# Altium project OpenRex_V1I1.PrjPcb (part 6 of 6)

## Sheet [24] - HEADERS, UART.SchDoc
size A2; DocumentNumber: 24; SheetNumber: 24; SheetTotal: 31
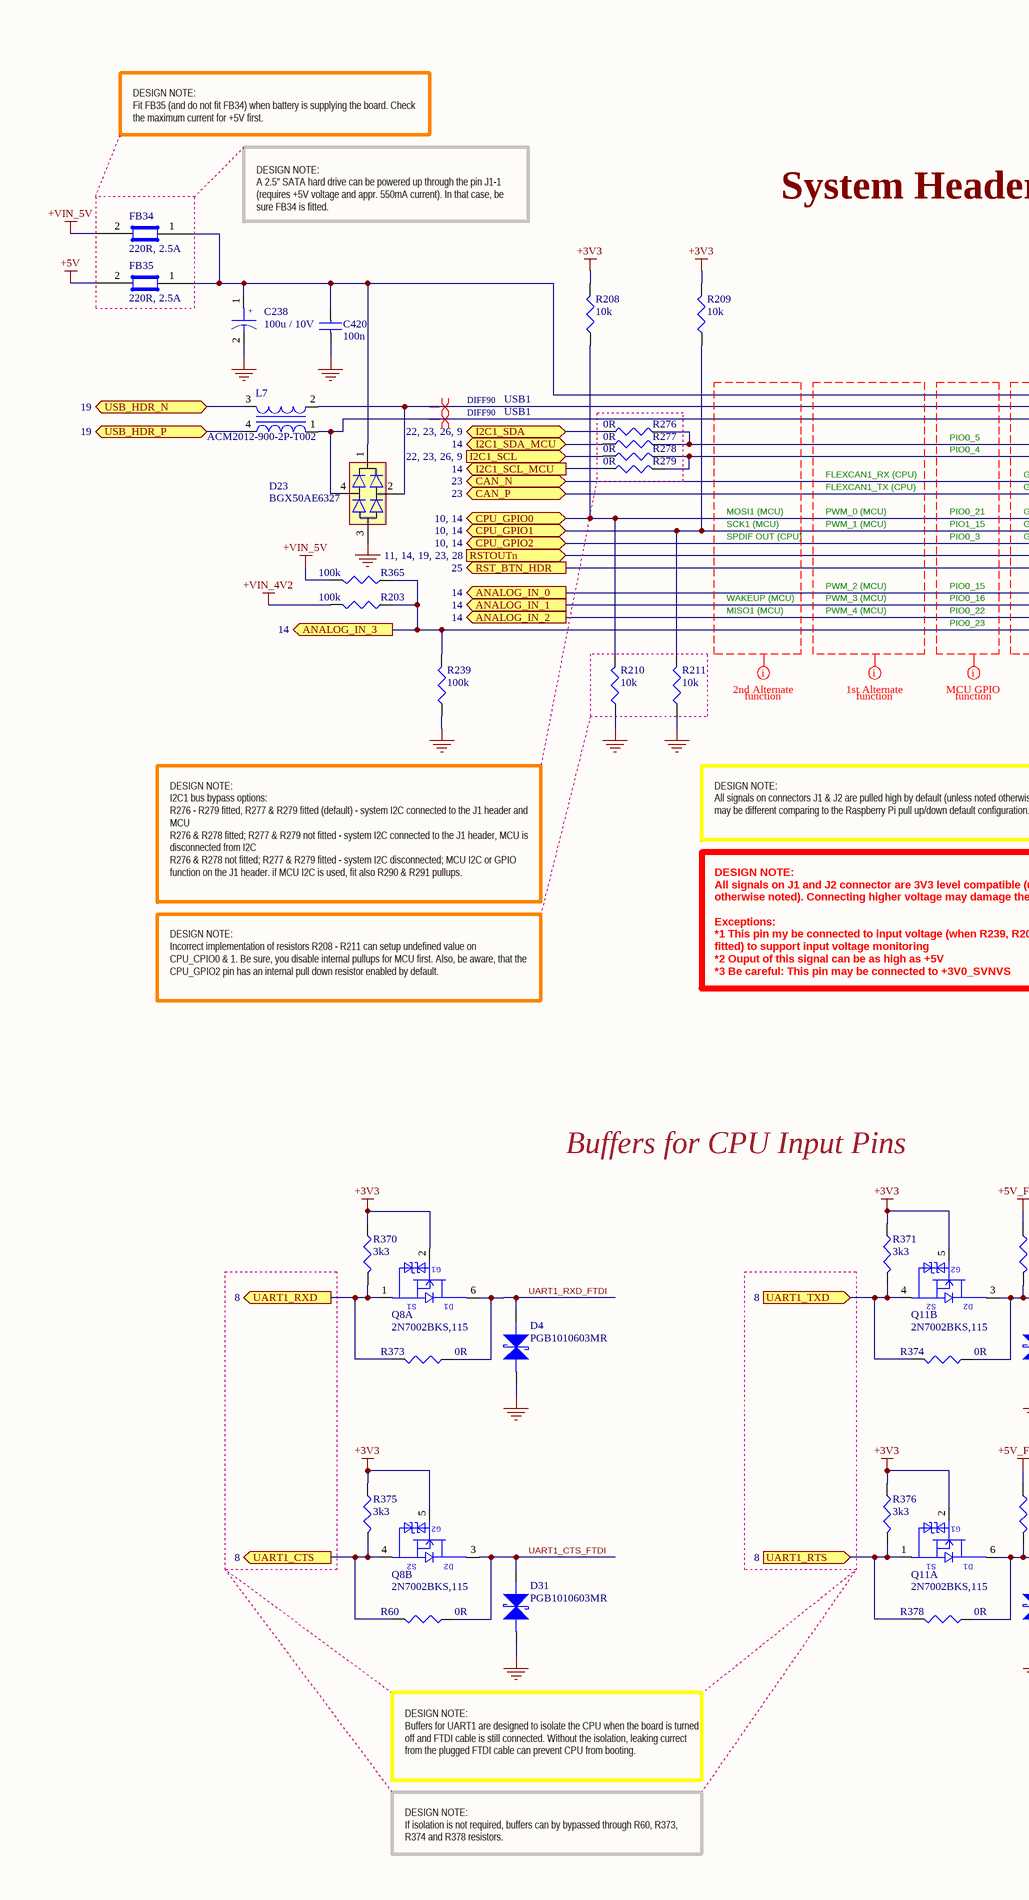
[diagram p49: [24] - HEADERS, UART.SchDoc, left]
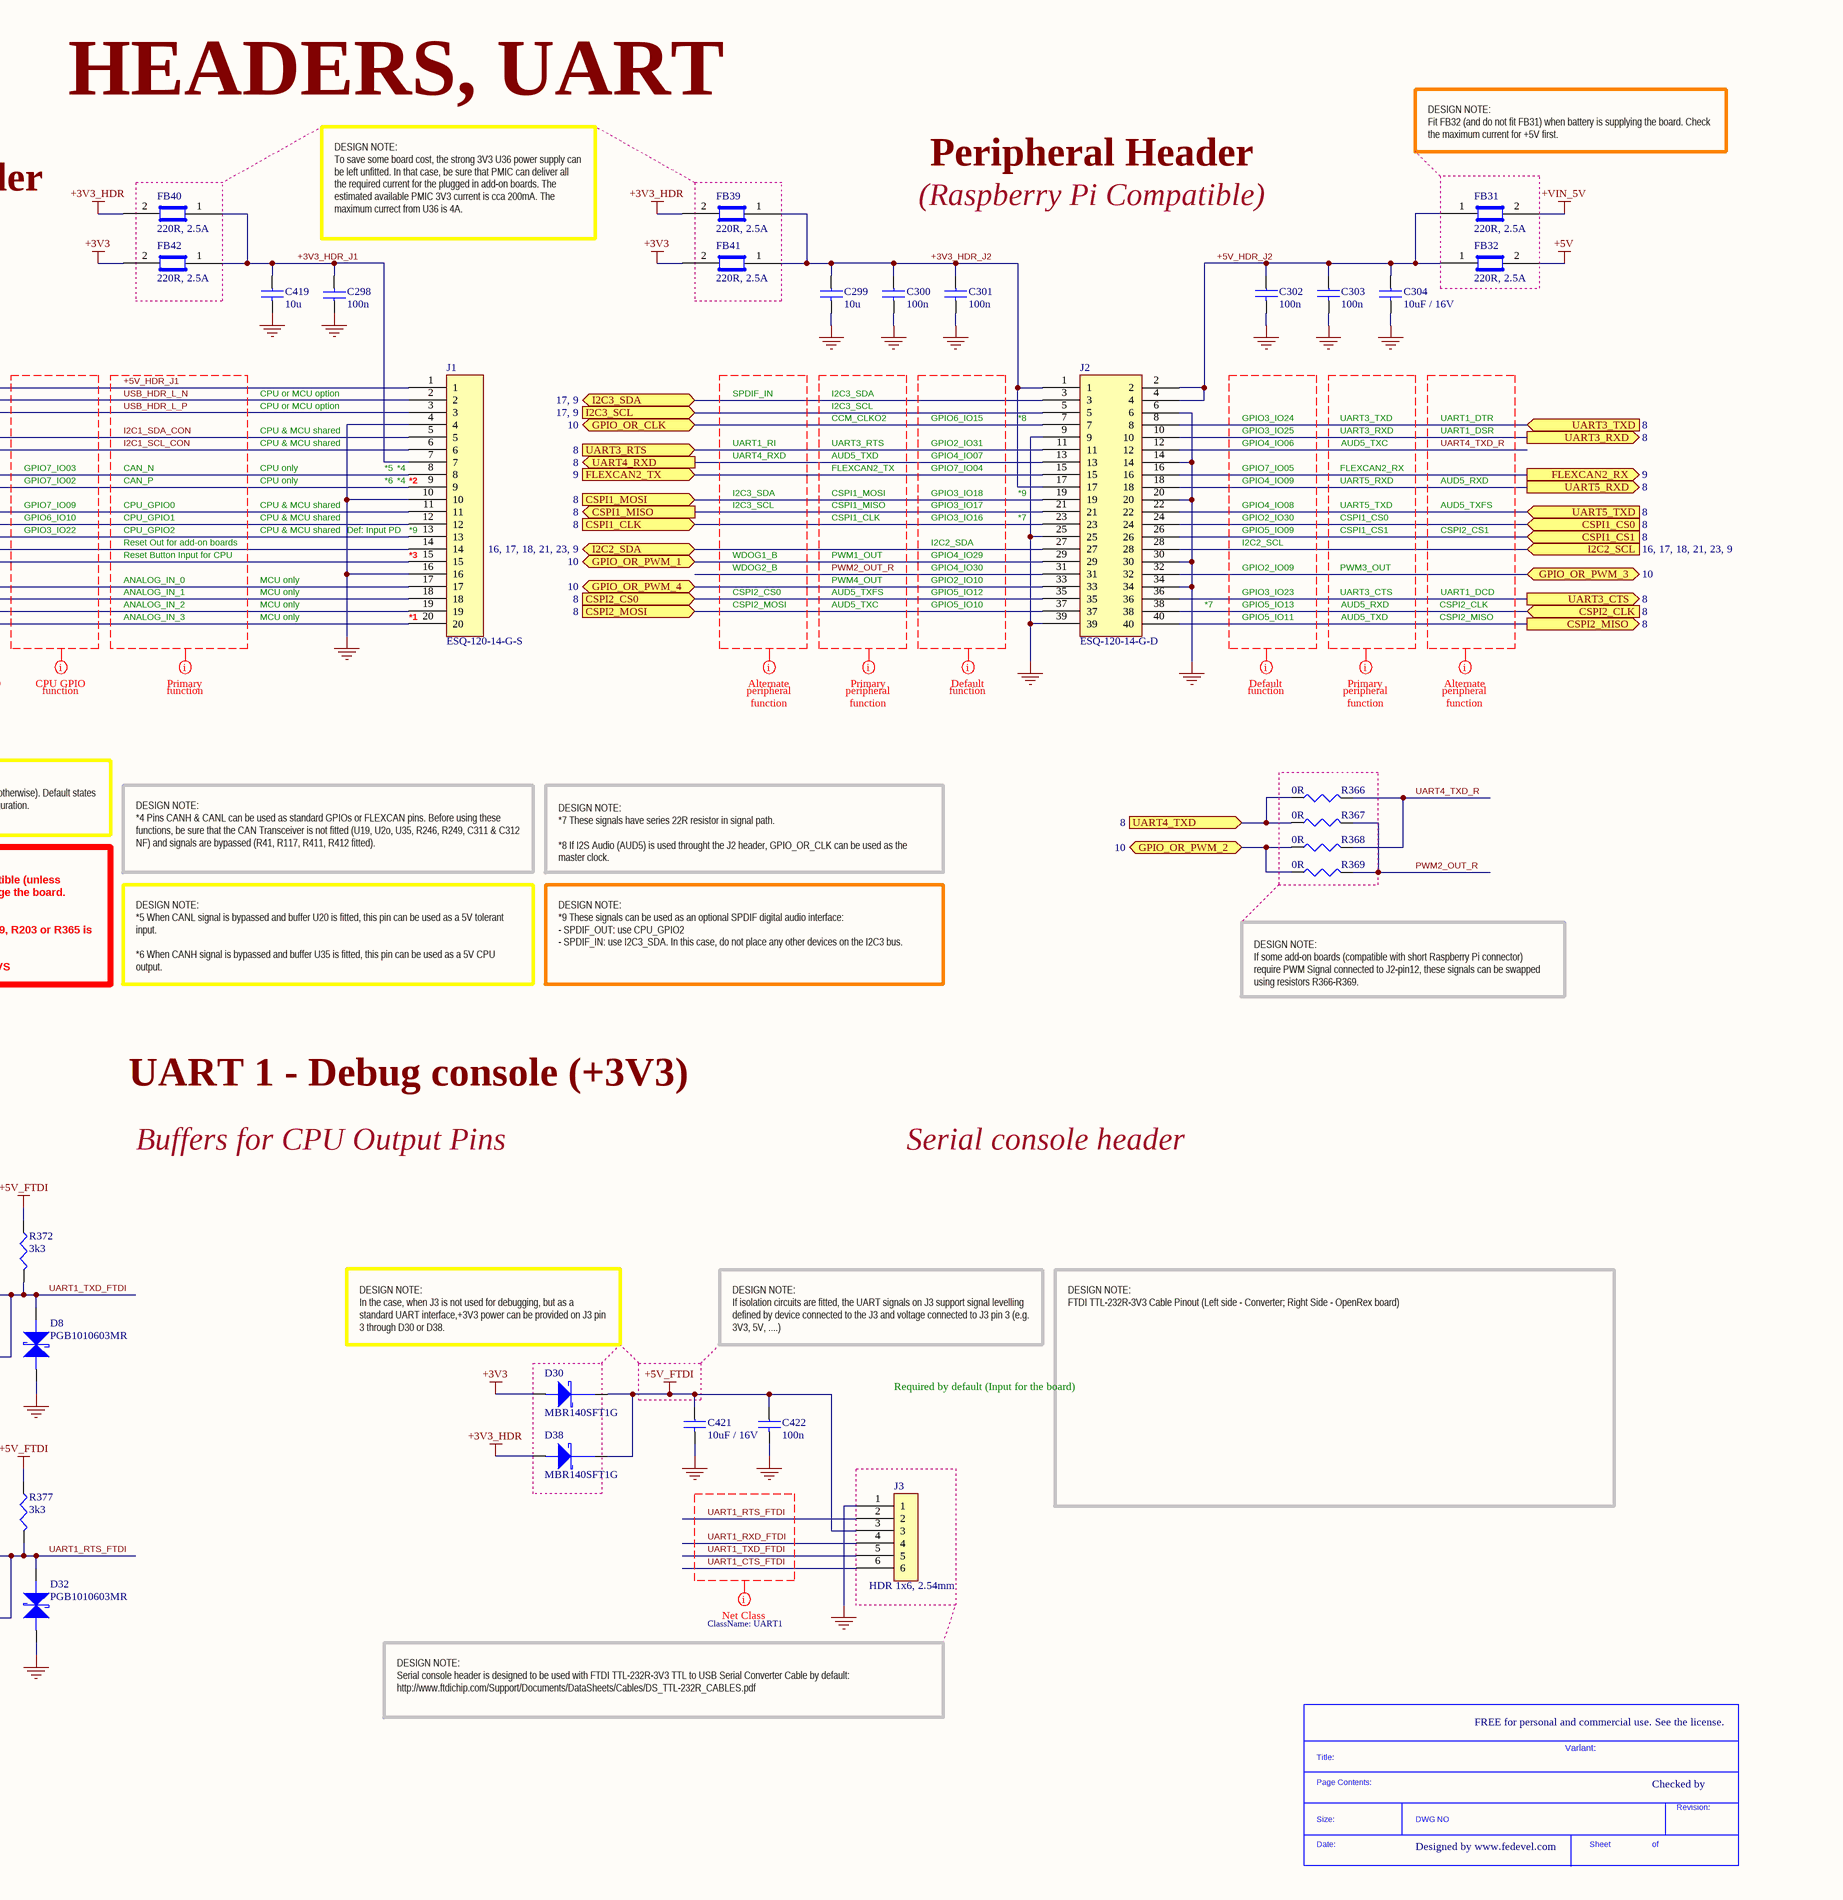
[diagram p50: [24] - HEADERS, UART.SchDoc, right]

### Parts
(Parts that share a designator on the sheet are numbered #1, #2 ... from top to bottom, then left to right.)
*#30  SDTitleBlock  (value not drawn)  (graphical)
C238  100u / 10V  [C2312]
C298  100n  [C0402]
C299  10u  [C0603]
C300  100n  [C0402]
C301  100n  [C0402]
C302  100n  [C0402]
C303  100n  [C0402]
C304  10uF / 16V  [C0805]
C419  10u  [C0603]
C420  100n  [C0402]
C421  10uF / 16V  [C0805]
C422  100n  [C0402]
D4  PGB1010603MR  [C0603]
D8  PGB1010603MR  [C0603]
D23  BGX50AE6327  [SOT143]
D30  MBR140SFT1G  [SOD-123FL]
D31  PGB1010603MR  [C0603]
D32  PGB1010603MR  [C0603]
D38  MBR140SFT1G  [SOD-123FL]
FB31  220R, 2.5A  [C0603]
FB32  220R, 2.5A  [C0603]
FB34  220R, 2.5A  [C0603]
FB35  220R, 2.5A  [C0603]
FB39  220R, 2.5A  [C0603]
FB40  220R, 2.5A  [C0603]
FB41  220R, 2.5A  [C0603]
FB42  220R, 2.5A  [C0603]
J1  ESQ-120-14-G-S  [ESQ-120-14-G-S]
J2  ESQ-120-14-G-D  [ESQ-120-14-G-D]
J3  HDR 1x6, 2.54mm  [Hdr_1x6_2.54mm]
L7  ACM2012-900-2P-T002  [ACM2012]
Q8  2N7002BKS,115  [SOT363]  (parts A,B of 2)
Q11  2N7002BKS,115  [SOT363]  (parts A,B of 2)
R60  0R  [R0402]
R203  100k  [R0402]
R208  10k  [R0402]
R209  10k  [R0402]
R210  10k  [R0402]
R211  10k  [R0402]
R239  100k  [R0402]
R276  0R  [R0402]
R277  0R  [R0402]
R278  0R  [R0402]
R279  0R  [R0402]
R365  100k  [R0402]
R366  0R  [R0402]
R367  0R  [R0402]
R368  0R  [R0402]
R369  0R  [R0402]
R370  3k3  [R0402]
R371  3k3  [R0402]
R372  3k3  [R0402]
R373  0R  [R0402]
R374  0R  [R0402]
R375  3k3  [R0402]
R376  3k3  [R0402]
R377  3k3  [R0402]
R378  0R  [R0402]

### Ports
ANALOG_IN_0 (out, see 14), ANALOG_IN_1 (out, see 14), ANALOG_IN_2 (out, see 14), ANALOG_IN_3 (out, see 14), CAN_N (bidir, see 23), CAN_P (bidir, see 23), CPU_GPIO0 (bidir, see 10, 14), CPU_GPIO1 (bidir, see 10, 14), CPU_GPIO2 (bidir, see 10, 14), CSPI1_CLK (in, see 8), CSPI1_CS0 (in, see 8), CSPI1_CS1 (in, see 8), CSPI1_MISO (out, see 8), CSPI1_MOSI (in, see 8), CSPI2_CLK (in, see 8), CSPI2_CS0 (in, see 8), CSPI2_MISO (out, see 8), CSPI2_MOSI (in, see 8), FLEXCAN2_RX (out, see 9), FLEXCAN2_TX (in, see 9), GPIO_OR_CLK (bidir, see 10), GPIO_OR_PWM_1 (bidir, see 10), GPIO_OR_PWM_2 (bidir, see 10), GPIO_OR_PWM_3 (bidir, see 10), GPIO_OR_PWM_4 (bidir, see 10), I2C1_SCL (see 22, 23, 26, 9), I2C1_SCL_MCU (out, see 14), I2C1_SDA (bidir, see 22, 23, 26, 9), I2C1_SDA_MCU (bidir, see 14), I2C2_SCL (see 16, 17, 18, 21, 23, 9), I2C2_SDA (bidir, see 16, 17, 18, 21, 23, 9), I2C3_SCL (see 17, 9), I2C3_SDA (bidir, see 17, 9), RST_BTN_HDR (out, see 25), RSTOUTn (see 11, 14, 19, 23, 28), UART1_CTS (out, see 8), UART1_RTS (in, see 8), UART1_RXD (out, see 8), UART1_TXD (in, see 8), UART3_CTS (out, see 8), UART3_RTS (in, see 8), UART3_RXD (out, see 8), UART3_TXD (in, see 8), UART4_RXD (out, see 8), UART4_TXD (in, see 8), UART5_RXD (out, see 8), UART5_TXD (in, see 8), USB_HDR_N (bidir, see 19), USB_HDR_P (bidir, see 19)

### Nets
+3V3: D30.2(Anode) FB41.2 FB42.2 Q8.2(GATE1) Q8.5(GATE2) Q11.2(GATE1) Q11.5(GATE2) R208.2 R209.2 R370.2 R371.2 R375.2 R376.2
+3V3_HDR: D38.2(Anode) FB39.2 FB40.2
+5V: FB32.2 FB35.2
+5V_FTDI: C421.1 C422.1 D30.1(Cathode) D38.1(Cathode) J3.3 R372.2 R377.2
+VIN_4V2: R203.2
+VIN_5V: FB31.2 FB34.2 R365.2
GND: C238.2 C298.1 C299.2 C300.2 C301.2 C302.2 C303.2 C304.2 C419.2 C420.2 C421.2 C422.2 D4.2 D8.2 D23.3 D31.2 D32.2 J1.4 J1.10 J1.16 J2.6 J2.9 J2.14 J2.20 J2.25 J2.30 J2.34 J2.39 J3.1 R210.1 R211.1 R239.1
+3V3_HDR_J1: C298.2 C419.1 FB40.1 FB42.1 J1.7
+3V3_HDR_J2: C299.1 C300.1 C301.1 FB39.1 FB41.1 J2.1 J2.17
+5V_HDR_J1: C238.1 C420.1 D23.1 FB34.1 FB35.1 J1.1
+5V_HDR_J2: C302.1 C303.1 C304.1 FB31.1 FB32.1 J2.2 J2.4
ANALOG_IN_0: J1.17 ; port ANALOG_IN_0
ANALOG_IN_1: J1.18 ; port ANALOG_IN_1
ANALOG_IN_2: J1.19 ; port ANALOG_IN_2
ANALOG_IN_3: J1.20 R203.1 R239.2 R365.1 ; port ANALOG_IN_3
CAN_N: J1.8 ; port CAN_N
CAN_P: J1.9 ; port CAN_P
CPU_GPIO0: J1.11 R208.1 R210.2 ; port CPU_GPIO0
CPU_GPIO1: J1.12 R209.1 R211.2 ; port CPU_GPIO1
CPU_GPIO2: J1.13 ; port CPU_GPIO2
CSPI1_CLK: J2.23 ; port CSPI1_CLK
CSPI1_CS0: J2.24 ; port CSPI1_CS0
CSPI1_CS1: J2.26 ; port CSPI1_CS1
CSPI1_MISO: J2.21 ; port CSPI1_MISO
CSPI1_MOSI: J2.19 ; port CSPI1_MOSI
CSPI2_CLK: J2.38 ; port CSPI2_CLK
CSPI2_CS0: J2.35 ; port CSPI2_CS0
CSPI2_MISO: J2.40 ; port CSPI2_MISO
CSPI2_MOSI: J2.37 ; port CSPI2_MOSI
FLEXCAN2_RX: J2.16 ; port FLEXCAN2_RX
FLEXCAN2_TX: J2.15 ; port FLEXCAN2_TX
GPIO_OR_CLK: J2.7 ; port GPIO_OR_CLK
GPIO_OR_PWM_1: J2.29 ; port GPIO_OR_PWM_1
GPIO_OR_PWM_2: R368.1 R369.1 ; port GPIO_OR_PWM_2
GPIO_OR_PWM_3: J2.32 ; port GPIO_OR_PWM_3
GPIO_OR_PWM_4: J2.33 ; port GPIO_OR_PWM_4
I2C1_SCL: R278.1 ; port I2C1_SCL
I2C1_SCL_CON: J1.6 R278.2 R279.2
I2C1_SCL_MCU: R279.1 ; port I2C1_SCL_MCU
I2C1_SDA: R276.1 ; port I2C1_SDA
I2C1_SDA_CON: J1.5 R276.2 R277.2
I2C1_SDA_MCU: R277.1 ; port I2C1_SDA_MCU
I2C2_SCL: J2.28 ; port I2C2_SCL
I2C2_SDA: J2.27 ; port I2C2_SDA
I2C3_SCL: J2.5 ; port I2C3_SCL
I2C3_SDA: J2.3 ; port I2C3_SDA
PWM2_OUT_R: J2.31 R367.2 R369.2
RST_BTN_HDR: J1.15 ; port RST_BTN_HDR
RSTOUTn: J1.14 ; port RSTOUTn
UART1_CTS: Q8.4(SOURCE2) R60.1 R375.1 ; port UART1_CTS
UART1_CTS_FTDI: D31.1 J3.6 Q8.3(DRAIN2) R60.2
UART1_RTS: Q11.1(SOURCE1) R376.1 R378.1 ; port UART1_RTS
UART1_RTS_FTDI: D32.1 J3.2 Q11.6(DRAIN1) R377.1 R378.2
UART1_RXD: Q8.1(SOURCE1) R370.1 R373.1 ; port UART1_RXD
UART1_RXD_FTDI: D4.1 J3.4 Q8.6(DRAIN1) R373.2
UART1_TXD: Q11.4(SOURCE2) R371.1 R374.1 ; port UART1_TXD
UART1_TXD_FTDI: D8.1 J3.5 Q11.3(DRAIN2) R372.1 R374.2
UART3_CTS: J2.36 ; port UART3_CTS
UART3_RTS: J2.11 ; port UART3_RTS
UART3_RXD: J2.10 ; port UART3_RXD
UART3_TXD: J2.8 ; port UART3_TXD
UART4_RXD: J2.13 ; port UART4_RXD
UART4_TXD: R366.1 R367.1 ; port UART4_TXD
UART4_TXD_R: J2.12 R366.2 R368.2
UART5_RXD: J2.18 ; port UART5_RXD
UART5_TXD: J2.22 ; port UART5_TXD
USB_HDR_L_N: D23.2 J1.2 L7.2
USB_HDR_L_P: D23.4 J1.3 L7.1
USB_HDR_N: L7.3 ; port USB_HDR_N
USB_HDR_P: L7.4 ; port USB_HDR_P

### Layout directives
differential pair; net class DIFF90; net class USB1: USB_HDR_L_N, USB_HDR_L_P
mark named Primary: (no net found under the mark), +5V_HDR_J1, I2C1_SCL_CON, I2C1_SDA_CON, PWM2_OUT_R, USB_HDR_L_N, USB_HDR_L_P
mark named Default: (no net found under the mark)
mark named Alternate: (no net found under the mark), UART4_TXD_R
mark named CPU GPIO: (no net found under the mark)
mark named 1st Alternate: (no net found under the mark)
mark named MCU GPIO: (no net found under the mark)
mark named 2nd Alternate: (no net found under the mark)
net class UART1: UART1_CTS_FTDI, UART1_RTS_FTDI, UART1_RXD_FTDI, UART1_TXD_FTDI

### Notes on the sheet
- DESIGN NOTE:
  Fit FB35 (and do not fit FB34) when battery is supplying the board. Check the maximum current for +5V first.
- HEADERS, UART
- Peripheral Header
- DESIGN NOTE:
  Fit FB32 (and do not fit FB31) when battery is supplying the board. Check the maximum current for +5V first.
- DESIGN NOTE:
  A 2.5" SATA hard drive can be powered up through the pin J1-1 (requires +5V voltage and appr. 550mA current). In that case, be sure FB34 is fitted.
- System Header
- DESIGN NOTE:
  To save some board cost, the strong 3V3 U36 power supply can be left unfitted. In that case, be sure that PMIC can deliver all the required current for the plugged in add-on boards. The estimated available PMIC 3V3 current is cca 200mA. The maximum currect from U36 is 4A.
- (Raspberry Pi Compatible)
- PIO0_5
- CPU & MCU shared
- CPU or MCU option
- SPDIF_IN
- I2C3_SCL
- I2C3_SDA
- CCM_CLKO2
- GPIO6_IO15
- *8
- GPIO3_IO24
- GPIO3_IO25
- UART3_TXD
- UART3_RXD
- UART1_DTR
- UART1_DSR
- FLEXCAN1_TX (CPU)
- FLEXCAN1_RX (CPU)
- PIO0_4
- GPIO7_IO02
- GPIO7_IO03
- CAN_P
- CAN_N
- CPU only
- *5
- *6
- (near J1) *4
- (near J1) *2
- UART1_RI
- UART4_RXD
- UART3_RTS
- FLEXCAN2_TX
- CSPI1_MOSI
- AUD5_TXD
- GPIO2_IO31
- GPIO7_IO04
- GPIO3_IO18
- GPIO4_IO07
- *9
- GPIO4_IO06
- GPIO4_IO09
- GPIO7_IO05
- UART5_RXD
- FLEXCAN2_RX
- AUD5_TXC
- AUD5_RXD
- MOSI1 (MCU)
- SCK1 (MCU)
- SPDIF OUT (CPU)
- PWM_0 (MCU)
- PWM_1 (MCU)
- PIO0_21
- PIO1_15
- PIO0_3
- GPIO7_IO09
- GPIO3_IO22
- GPIO6_IO10
- Reset Button Input for CPU
- Reset Out for add-on boards
- CPU_GPIO0
- CPU_GPIO1
- CPU_GPIO2
- (near J1) Def: Input PD
- (near J1) *3
- (near J1) *9
- WDOG1_B
- CSPI1_MISO
- CSPI1_CLK
- PWM1_OUT
- GPIO3_IO17
- GPIO3_IO16
- I2C2_SDA
- GPIO4_IO29
- *7
- GPIO4_IO08
- GPIO2_IO30
- GPIO5_IO09
- I2C2_SCL
- UART5_TXD
- CSPI1_CS0
- CSPI1_CS1
- AUD5_TXFS
- CSPI2_CS1
- MISO1 (MCU)
- WAKEUP (MCU)
- PWM_2 (MCU)
- PWM_3 (MCU)
- PWM_4 (MCU)
- PIO0_15
- PIO0_16
- PIO0_22
- PIO0_23
- ANALOG_IN_0
- ANALOG_IN_1
- ANALOG_IN_2
- ANALOG_IN_3
- MCU only
- (near J1) *1
- WDOG2_B
- CSPI2_CS0
- CSPI2_MOSI
- PWM4_OUT
- GPIO2_IO10
- GPIO4_IO30
- GPIO5_IO12
- GPIO5_IO10
- GPIO3_IO23
- GPIO2_IO09
- GPIO5_IO13
- GPIO5_IO11
- UART3_CTS
- PWM3_OUT
- CSPI2_CLK
- CSPI2_MISO
- UART1_DCD
- function
- peripheral
- DESIGN NOTE:
  All signals on connectors J1 & J2 are pulled high by default (unless noted otherwise). Default states may be different comparing to the Raspberry Pi pull up/down default configuration.
- DESIGN NOTE:
  *4 Pins CANH & CANL can be used as standard GPIOs or FLEXCAN pins. Before using these functions, be sure that the CAN Transceiver is not fitted (U19, U2o, U35, R246, R249, C311 & C312 NF) and signals are bypassed (R41, R117, R411, R412 fitted).
- DESIGN NOTE:
  *7 These signals have series 22R resistor in signal path.
  *8 If I2S Audio (AUD5) is used throught the J2 header, GPIO_OR_CLK can be used as the master clock.
- DESIGN NOTE:
  I2C1 bus bypass options:
  R276 - R279 fitted, R277 & R279 fitted (default) - system I2C connected to the J1 header and MCU
  R276 & R278 fitted; R277 & R279 not fitted - system I2C connected to the J1 header, MCU is disconnected from I2C
  R276 & R278 not fitted; R277 & R279 fitted - system I2C disconnected; MCU I2C or GPIO function on the J1 header. if MCU I2C is used, fit also R290 & R291 pullups.
- DESIGN NOTE:
  Incorrect implementation of resistors R208 - R211 can setup undefined value on CPU_CPIO0 & 1. Be sure, you disable internal pullups for MCU first. Also, be aware, that the CPU_GPIO2 pin has an internal pull down resistor enabled by default.
- DESIGN NOTE:
  All signals on J1 and J2 connector are 3V3 level compatible (unless otherwise noted). Connecting higher voltage may damage the board.
  Exceptions:
  *1 This pin my be connected to input voltage (when R239, R203 or R365 is fitted) to support input voltage monitoring
  *2 Ouput of this signal can be as high as +5V
  *3 Be careful: This pin may be connected to +3V0_SVNVS
- DESIGN NOTE:
  *5 When CANL signal is bypassed and buffer U20 is fitted, this pin can be used as a 5V tolerant input.
  *6 When CANH signal is bypassed and buffer U35 is fitted, this pin can be used as a 5V CPU output.
- DESIGN NOTE:
  *9 These signals can be used as an optional SPDIF digital audio interface:
  - SPDIF_OUT: use CPU_GPIO2
  - SPDIF_IN: use I2C3_SDA. In this case, do not place any other devices on the I2C3 bus.
- DESIGN NOTE:
  If some add-on boards (compatible with short Raspberry Pi connector) require PWM Signal connected to J2-pin12, these signals can be swapped using resistors R366-R369.
- UART 1 - Debug console (+3V3)
- Buffers for CPU Input Pins
- Buffers for CPU Output Pins
- Serial console header
- DESIGN NOTE:
  In the case, when J3 is not used for debugging, but as a standard UART interface,+3V3 power can be provided on J3 pin 3 through D30 or D38.
- DESIGN NOTE:
  If isolation circuits are fitted, the UART signals on J3 support signal levelling defined by device connected to the J3 and voltage connected to J3 pin 3 (e.g. 3V3, 5V, ....)
- DESIGN NOTE:
  FTDI TTL-232R-3V3 Cable Pinout (Left side - Converter; Right Side - OpenRex board)
- Required by default (Input for the board)
- DESIGN NOTE:
  Serial console header is designed to be used with FTDI TTL-232R-3V3 TTL to USB Serial Converter Cable by default:
  http://www.ftdichip.com/Support/Documents/DataSheets/Cables/DS_TTL-232R_CABLES.pdf
- FREE for personal and commercial use. See the license.
- DESIGN NOTE:
  Buffers for UART1 are designed to isolate the CPU when the board is turned off and FTDI cable is still connected. Without the isolation, leaking currect from the plugged FTDI cable can prevent CPU from booting.
- Variant:
- Checked by
- DESIGN NOTE:
  If isolation is not required, buffers can by bypassed through R60, R373, R374 and R378 resistors.
- Designed by www.fedevel.com

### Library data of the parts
C238 = TPSC107K010R0150: CAP TANT 100UF 10V 10% 2312; Manufacturer: AVX Corporation; Manufacturer Size Code: C; Capacitance: 100µF; ESR (Equivalent Series Resistance): 150 mOhm; Type: Molded; .Creator: MM
C298 C300-C303 C420 C422 = C1005X5R1H104K: CAP CER .10UF 50V X5R 10% 0402; Manufacturer: TDK Corporation; Capacitance: 0.1µF; Value: 100nF; .Checked PCB: used
C299 C419 = C1608X5R0J106M: CAP CER 10UF 6.3V X5R 20% 0603; Manufacturer: TDK Corporation; Capacitance: 10µF; Value: 10µF; .Checked PCB: used
C304 C421 = C2012X5R1C106M: CAP CER 10UF 16V 20% X5R 0805; Manufacturer: TDK Corporation; Manufacturer Part Number: C2012X5R1C106M/1.25; Capacitance: 10µF; .Checked PCB: used
D4 D8 D31 D32 = PGB1010603MR: SUPPRESSOR ESD 24VDC 0603 SMD; Manufacturer: Littelfuse Inc; Voltage - Reverse Standoff (Typ): 24V; Polarization: Bidirectional; .Creator: MM; .Checked PCB: used
D23 = BGX50AE6327: DIODE SWITCHING 50V SOT-143; Manufacturer: Infineon Technologies; .Checked PCB: used; Current - DC Forward (If): 140mA; Diode Type: Single Phase; Speed: Small Signal =< 200mA (Io), Any Speed; Reverse Recovery Time (trr): 6ns
D30 D38 = MBR140SFT1G: DIODE SCHOTTKY 40V 1A SOD123L; Manufacturer: ON Semiconductor; Voltage - Forward (Vf) (Max) @ If: 550mV @ 1A; Speed: Fast Recovery =< 500ns, > 200mA (Io); Current - Reverse Leakage @ Vr: 500µA @ 40V; .Creator: MM
FB31 FB32 FB34 FB35 FB39-FB42 = BLM18SG221TN1D: FERRITE CHIP 220 OHM 2500MA 0603; Manufacturer: Murata Electronics North America; Impedance @ Frequency: 220 Ohm @ 100MHz; DC Resistance (DCR): 40 mOhm Max; Filter Type: Differential Mode - Single; Number of Lines: 1; .Checked PCB: used
J1 = ESQ-120-14-G-S: CONN RCPT 20POS .100" DUAL GOLD; Manufacturer: Samtec Inc.; Connector Type: Receptacle; Number of Positions: 20; Number of Positions Loaded: All; Pitch: 0.100" (2.54mm); .Creator: MM; .Checked PCB: MM, paper model not checked
J2 = ESQ-120-14-G-D: CONN RCPT 40POS .100" DUAL GOLD; Manufacturer: Samtec Inc.; Connector Type: Receptacle; Number of Positions: 40; Number of Positions Loaded: All; Pitch: 0.100" (2.54mm); .Creator: MM
J3 = 68001-206HLF: CONN HEADER 6POS .100 STR 15AU; Manufacturer: FCI; Connector Type: Header, Unshrouded; Number of Positions: 6; Number of Positions Loaded: All; Pitch: 0.100" (2.54mm); .Creator: MM
L7 = ACM2012-900-2P-T002: CHOKE COMM MODE 90 OHM .4A SMD; Manufacturer: TDK Corporation; Filter Type: Data, Signal Line; Number of Lines: 2; Current: 400mA; DC Resistance (DCR): 190 mOhm Max; Impedance: 90 Ohm; Resistance (Ohms): 8.2K; Power (Watts): 0.063W, 1/16W; Temperature Coefficient: ±100ppm/°C; Tolerance: ±1%; .Checked PCB: used
Q8 Q11 = 2N7002BKS,115: MOSFET 2N-CH 60V 0.3A 6TSSOP; Manufacturer: NXP Semiconductors; FET Type: 2 N-Channel (Dual); FET Feature: Logic Level Gate; Current - Continuous Drain (Id) @ 25°C: 300mA; Rds On (Max) @ Id, Vgs: 1.6 Ohm @ 500mA, 10V; Vgs(th) (Max) @ Id: 2.1V @ 250µA; Gate Charge (Qg) @ Vgs: 0.6nC @ 4.5V; Input Capacitance (Ciss) @ Vds: 50pF @ 10V; Power - Max: 295mW; .Creator: MM
R60 R276-R279 R366-R369 R373 R374 R378 = RC0402JR-070RL: RES 0.0 OHM 1/16W 0402 SMD; Manufacturer: Yageo; Resistance (Ohms): 0.0; Power (Watts): 0.063W, 1/16W; Tolerance: Jumper; .Checked PCB: used
R203 R239 R365 = RMCF0402FT100K: RES 100K OHM 1/16W 1% 0402 SMD; Manufacturer: Stackpole Electronics Inc; Power (Watts): 0.063W, 1/16W; .Checked PCB: used; Temperature Coefficient: ±100ppm/°C
R208-R211 = RC0402FR-0710KL: RES 10.0K OHM 1/16W 1% 0402 SMD; Manufacturer: Yageo; Power (Watts): 0.063W, 1/16W; .Checked PCB: used; Temperature Coefficient: ±100ppm/°C
R370-R372 R375-R377 = RC0402FR-073K3L: RES 3.30K OHM 1/16W 1% 0402 SMD; Manufacturer: Yageo; Resistance (Ohms): 3.3K; Power (Watts): 0.063W, 1/16W; .Checked PCB: used; Temperature Coefficient: ±100ppm/°C

## Sheet [29] - POWER SEQUENCING.SchDoc
size A2; DocumentNumber: 29; SheetNumber: 29; SheetTotal: 31
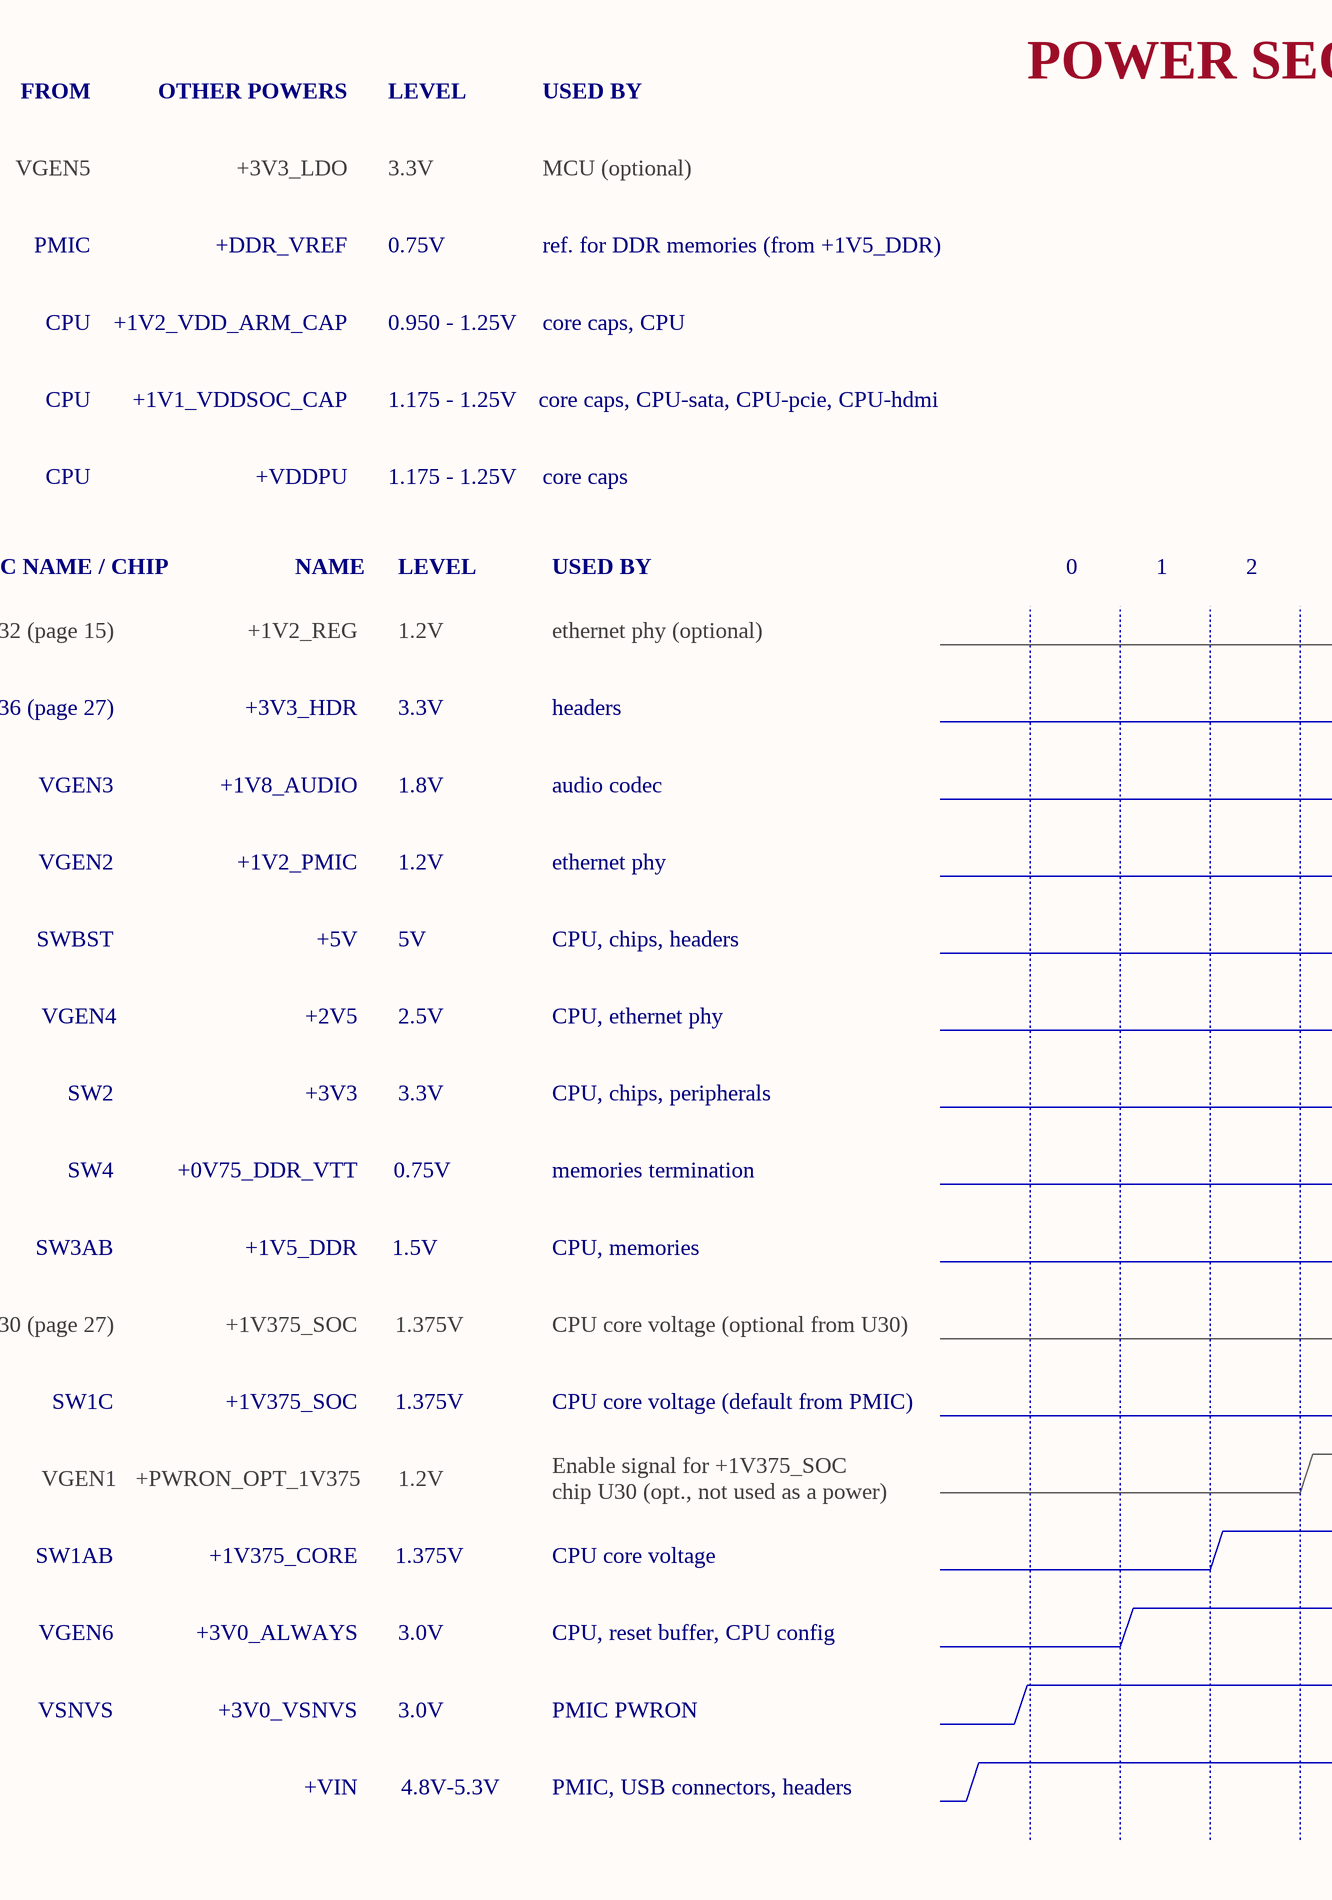
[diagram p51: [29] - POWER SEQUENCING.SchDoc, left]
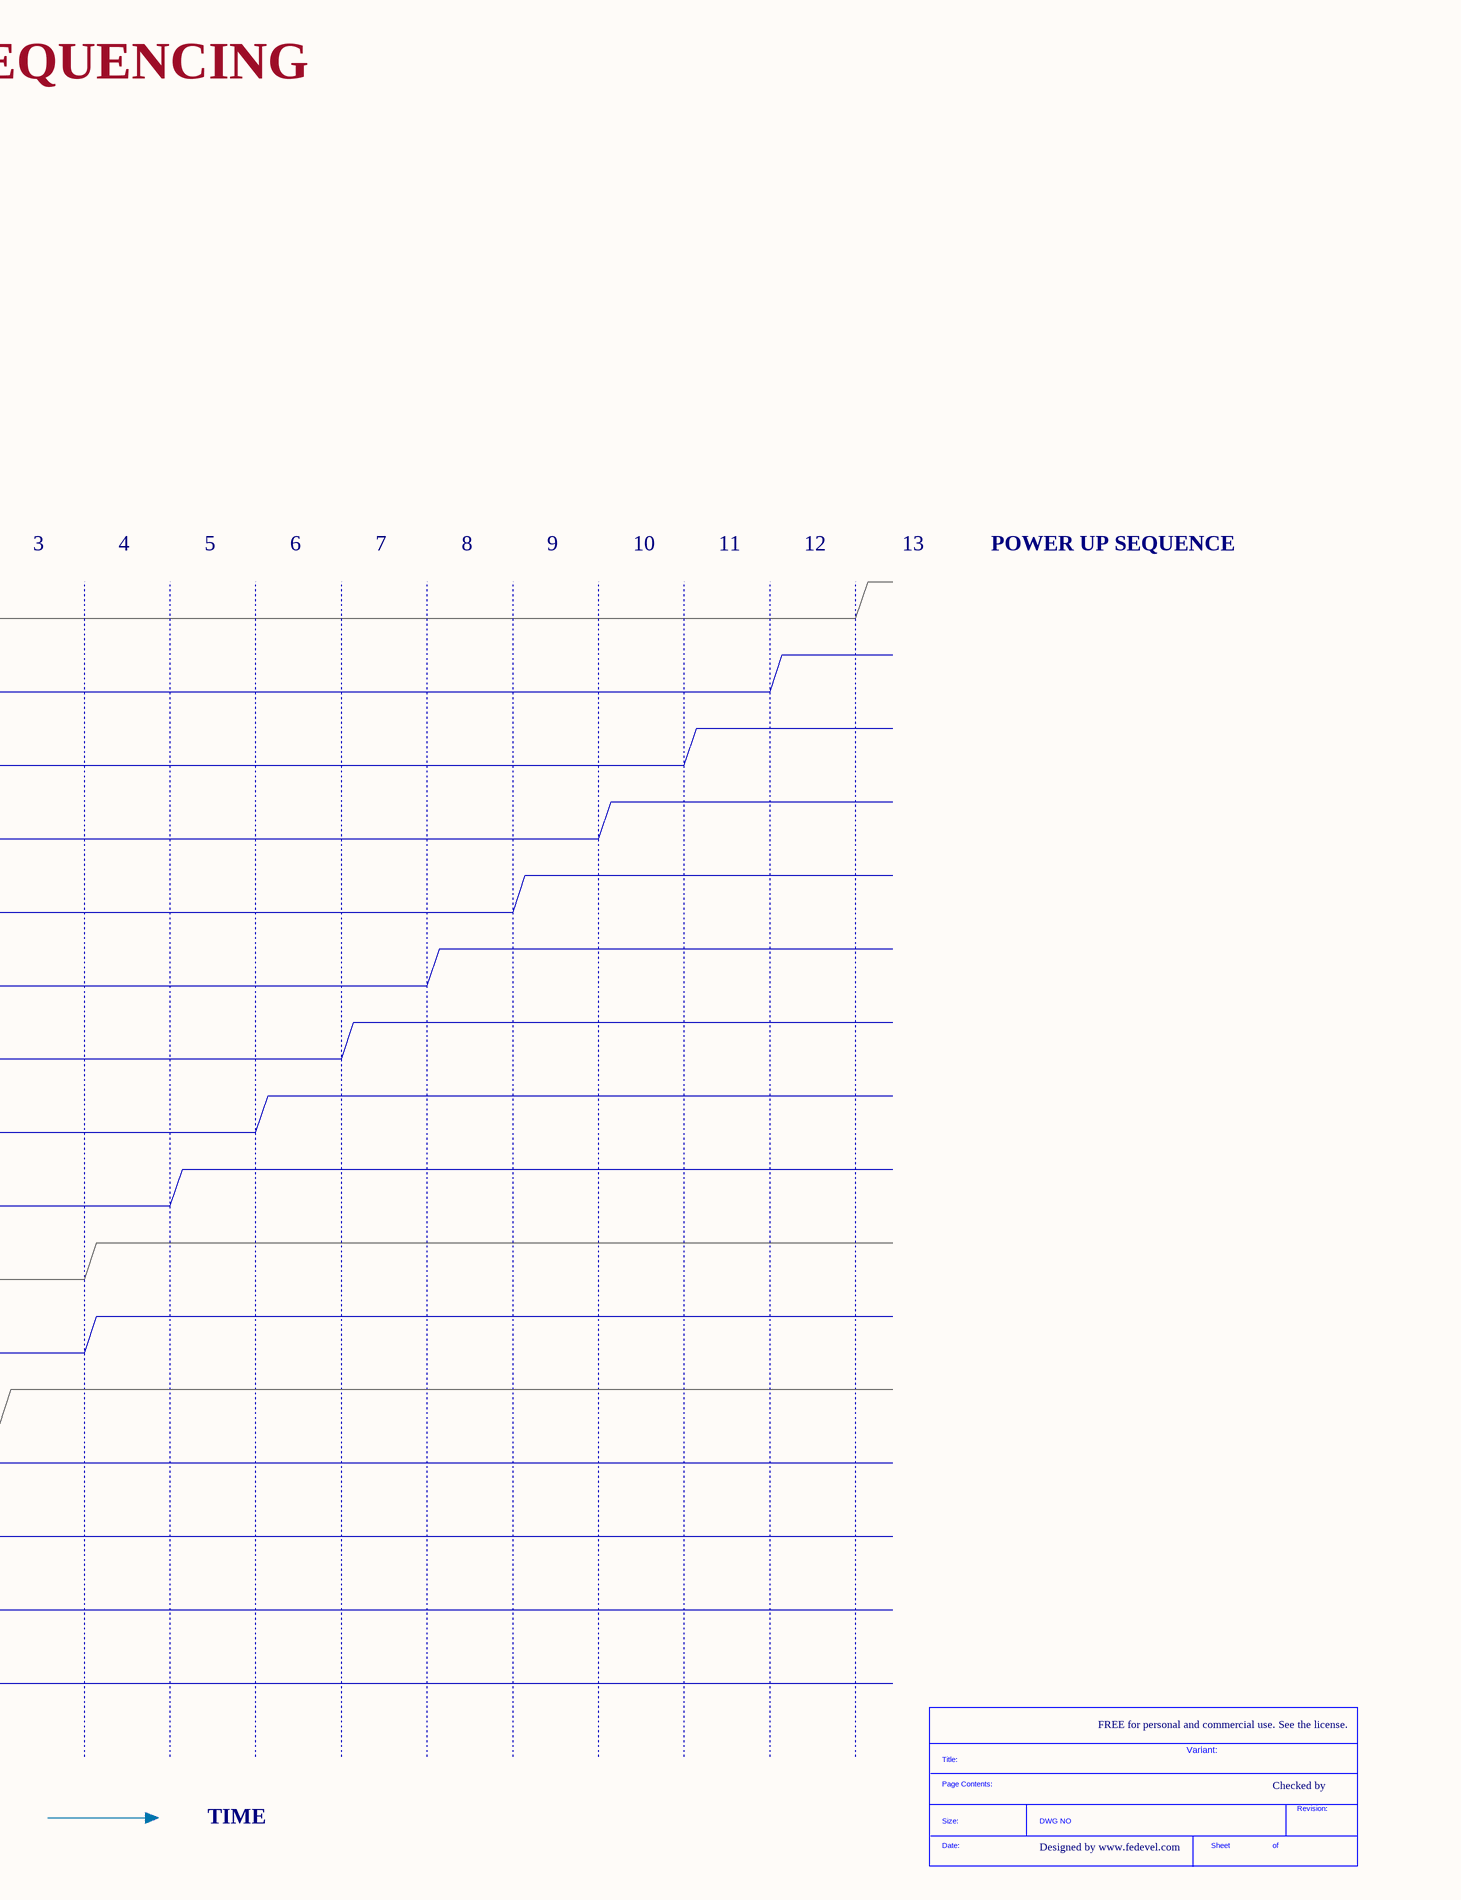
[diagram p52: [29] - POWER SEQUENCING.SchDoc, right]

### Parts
(Parts that share a designator on the sheet are numbered #1, #2 ... from top to bottom, then left to right.)
*#31  SDTitleBlock  (value not drawn)  (graphical)

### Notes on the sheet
- POWER SEQUENCING
- FROM
- OTHER POWERS
- LEVEL
- USED BY
- VGEN5
- +3V3_LDO
- 3.3V
- MCU (optional)
- PMIC
- +DDR_VREF
- 0.75V
- ref. for DDR memories (from +1V5_DDR)
- CPU
- +1V2_VDD_ARM_CAP
- 0.950 - 1.25V
- core caps, CPU
- +1V1_VDDSOC_CAP
- 1.175 - 1.25V
- core caps, CPU-sata, CPU-pcie, CPU-hdmi
- +VDDPU
- core caps
- PMIC NAME / CHIP
- NAME
- 0
- 1
- 2
- 3
- 4
- 5
- 6
- 7
- 8
- 9
- 10
- 11
- 12
- 13
- POWER UP SEQUENCE
- U32 (page 15)
- +1V2_REG
- 1.2V
- ethernet phy (optional)
- U36 (page 27)
- +3V3_HDR
- headers
- VGEN3
- +1V8_AUDIO
- 1.8V
- audio codec
- VGEN2
- +1V2_PMIC
- ethernet phy
- SWBST
- +5V
- 5V
- CPU, chips, headers
- VGEN4
- +2V5
- 2.5V
- CPU, ethernet phy
- SW2
- +3V3
- CPU, chips, peripherals
- SW4
- +0V75_DDR_VTT
- memories termination
- SW3AB
- +1V5_DDR
- 1.5V
- CPU, memories
- U30 (page 27)
- +1V375_SOC
- 1.375V
- CPU core voltage (optional from U30)
- SW1C
- CPU core voltage (default from PMIC)
- VGEN1
- +PWRON_OPT_1V375
- Enable signal for +1V375_SOC
- chip U30 (opt., not used as a power)
- SW1AB
- +1V375_CORE
- CPU core voltage
- VGEN6
- +3V0_ALWAYS
- 3.0V
- CPU, reset buffer, CPU config
- VSNVS
- +3V0_VSNVS
- PMIC PWRON
- +VIN
- 4.8V-5.3V
- PMIC, USB connectors, headers
- FREE for personal and commercial use. See the license.
- Variant:
- Checked by
- TIME
- Designed by www.fedevel.com

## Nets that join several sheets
+0V75_DDR_VTT: [03] - CPU - DDR3, DDR3 MEM (47 pins), [26] - PWR PMIC (6 pins)
+1V1_VDDSOC_CAP: [04] - CPU - PCIE, USB (C78.1 FB1.1 R13.1), [05] - CPU - HDMI, LVDS (C246.1 R27.1), [06] - CPU - ETHERNET, SATA (R18.1), [12] - CPU - POWER (16 pins)
+1V2_PMIC: [15] - ETHERNET PHY (R353.2), [26] - PWR PMIC (C333.1 TP33.1 U9.18)
+1V5_DDR: [03] - CPU - DDR3, DDR3 MEM (147 pins), [11] - CPU - JTAG, CONTROL (R302.2), [12] - CPU - POWER (13 pins), [18] - PCIE MINI (FB10.2), [26] - PWR PMIC (10 pins), [21] - AUDIO (FB20.1)
+1V8_AUDIO: [26] - PWR PMIC (C334.1 TP34.1 U9.26), [21] - AUDIO (FB11.2 FB26.2)
+1V375_CORE: [12] - CPU - POWER (28 pins), [15] - ETHERNET PHY (FB8.1), [26] - PWR PMIC (7 pins), [27] - PWR 1V375 OPT, 3V3 OPT (R340.2)
+1V375_SOC: [12] - CPU - POWER (21 pins), [26] - PWR PMIC (6 pins), [27] - PWR 1V375 OPT, 3V3 OPT (5 pins)
+2V5: [04] - CPU - PCIE, USB (C244.1 R14.1), [05] - CPU - HDMI, LVDS (C247.1 R29.1 R36.1), [06] - CPU - ETHERNET, SATA (C209.1 R19.1), [12] - CPU - POWER (C153.1 R74.2 R78.2 R80.2), [15] - ETHERNET PHY (FB6.1), [26] - PWR PMIC (C336.1 TP35.1 U9.28)
+3V0_ALWAYS: [11] - CPU - JTAG, CONTROL (14 pins), [12] - CPU - POWER (6 pins), [26] - PWR PMIC (5 pins), [27] - PWR 1V375 OPT, 3V3 OPT (R405.2)
+3V0_VSNVS: [25] - LEDS, BUTTONS (R347.2), [26] - PWR PMIC (C343.1 R262.2 R385.2 U9.43)
+3V3: [17] - LVDS, CSI, LCD, TSC (FB14.1 FB16.1), [04] - CPU - PCIE, USB (R116.2 R260.2), [05] - CPU - HDMI, LVDS (R21.2 R118.2), [08] - CPU - SPI, UART (R319.2), [10] - CPU - GPIO, PWM, LEDS, BUTTONS (6 pins), [09] - CPU - SD, AUDIO, I2C, CAN (10 pins), [11] - CPU - JTAG, CONTROL (13 pins), [12] - CPU - POWER (21 pins), [18] - PCIE MINI (5 pins), [15] - ETHERNET PHY (FB7.1 R355.1), [19] - USB (FB19.1 R198.2), [14] - MCU (6 pins), [20] - ETHERNET, SATA (C273.1 J6.14 J6.16), [25] - LEDS, BUTTONS (16 pins), [26] - PWR PMIC (13 pins), [22] - SD CARD, SPI, FLASH, EEPROM, (20 pins), [23] - SENSORS, CAN, IR (14 pins), [16] - HDMI (5 pins), [21] - AUDIO (C280.1 FB12.1 FB13.2), [24] - HEADERS, UART (13 pins)
+3V3_HDR: [27] - PWR 1V375 OPT, 3V3 OPT (7 pins), [24] - HEADERS, UART (D38.2 FB39.2 FB40.2)
+3V3_LDO: [14] - MCU (FB29.1), [26] - PWR PMIC (C337.1 TP36.1 U9.39)
+3V3_MCU: [14] - MCU (14 pins), [25] - LEDS, BUTTONS (R380.2)
+5V: [04] - CPU - PCIE, USB (C73.1 C75.1 U1.D10 U1.E9), [18] - PCIE MINI (FB17.1), [19] - USB (C237.1 FB38.1 R215.1), [26] - PWR PMIC (6 pins), [23] - SENSORS, CAN, IR (FB44.1), [16] - HDMI (C213.1 U12.1), [24] - HEADERS, UART (FB32.2 FB35.2)
+5V_USB_OTG: [19] - USB (5 pins), [28] - PWR IN, MECH, DOC (FB2.2 Q2.3)
+DDR_VREF: [03] - CPU - DDR3, DDR3 MEM (22 pins), [26] - PWR PMIC (R345.1)
+VIN_4V2: [15] - ETHERNET PHY (R354.1), [26] - PWR PMIC (32 pins), [27] - PWR 1V375 OPT, 3V3 OPT (15 pins), [28] - PWR IN, MECH, DOC (C381.1 D9.1 TP38.1), [24] - HEADERS, UART (R203.2)
+VIN_5V: [18] - PCIE MINI (FB37.1), [19] - USB (C252.1 FB23.1 FB24.2 U17.7), [28] - PWR IN, MECH, DOC (8 pins), [24] - HEADERS, UART (FB31.2 FB34.2 R365.2)
GND: [17] - LVDS, CSI, LCD, TSC (26 pins), [04] - CPU - PCIE, USB (13 pins), [05] - CPU - HDMI, LVDS (10 pins), [06] - CPU - ETHERNET, SATA (C81.2 C82.2 C209.2 R99.1), [03] - CPU - DDR3, DDR3 MEM (164 pins), [11] - CPU - JTAG, CONTROL (28 pins), [12] - CPU - POWER (194 pins), [18] - PCIE MINI (42 pins), [15] - ETHERNET PHY (41 pins), [19] - USB (52 pins), [07] - CPU - CSI, DISP (R160.1), [14] - MCU (23 pins), [20] - ETHERNET, SATA (12 pins), [25] - LEDS, BUTTONS (15 pins), [26] - PWR PMIC (66 pins), [27] - PWR 1V375 OPT, 3V3 OPT (29 pins), [28] - PWR IN, MECH, DOC (16 pins), [22] - SD CARD, SPI, FLASH, EEPROM, (18 pins), [23] - SENSORS, CAN, IR (56 pins), [16] - HDMI (28 pins), [21] - AUDIO (23 pins), [24] - HEADERS, UART (32 pins)
+PWRON_1V375_OPT: [26] - PWR PMIC (C331.1 U9.16), [27] - PWR 1V375 OPT, 3V3 OPT (R341.2)
ANALOG_IN_0: [14] - MCU (R282.2 U25.1), [24] - HEADERS, UART (J1.17)
ANALOG_IN_1: [14] - MCU (U6.26), [24] - HEADERS, UART (J1.18)
ANALOG_IN_2: [14] - MCU (U6.20), [24] - HEADERS, UART (J1.19)
ANALOG_IN_3: [14] - MCU (U6.27), [24] - HEADERS, UART (J1.20 R203.1 R239.2 R365.1)
AUD3_CLK: [09] - CPU - SD, AUDIO, I2C, CAN (R206.2), [21] - AUDIO (U14.21)
AUD3_RXD: [09] - CPU - SD, AUDIO, I2C, CAN (U1.N3), [21] - AUDIO (U14.25)
AUD3_TXC: [09] - CPU - SD, AUDIO, I2C, CAN (R124.2), [21] - AUDIO (U14.24)
AUD3_TXD: [09] - CPU - SD, AUDIO, I2C, CAN (U1.P2), [21] - AUDIO (U14.26)
AUD3_TXFS: [09] - CPU - SD, AUDIO, I2C, CAN (U1.N4), [21] - AUDIO (U14.23)
CAN_N: [23] - SENSORS, CAN, IR (C312.1 R117.2 R249.1 U19.6), [24] - HEADERS, UART (J1.8)
CAN_P: [23] - SENSORS, CAN, IR (C311.1 R41.2 R246.2 U19.7), [24] - HEADERS, UART (J1.9)
COMP_INT: [10] - CPU - GPIO, PWM, LEDS, BUTTONS (R240.1 U1.N25), [23] - SENSORS, CAN, IR (R241.2 R242.2)
CPU_GPIO0: [10] - CPU - GPIO, PWM, LEDS, BUTTONS (U1.B17), [14] - MCU (R227.2), [24] - HEADERS, UART (J1.11 R208.1 R210.2)
CPU_GPIO1: [10] - CPU - GPIO, PWM, LEDS, BUTTONS (U1.B16), [14] - MCU (R228.2), [24] - HEADERS, UART (J1.12 R209.1 R211.2)
CPU_GPIO2: [10] - CPU - GPIO, PWM, LEDS, BUTTONS (U1.E23), [14] - MCU (R273.2), [24] - HEADERS, UART (J1.13)
CSI_CLK0_N: [17] - LVDS, CSI, LCD, TSC (R125.1), [07] - CPU - CSI, DISP (U1.F4)
CSI_CLK0_P: [17] - LVDS, CSI, LCD, TSC (R127.1), [07] - CPU - CSI, DISP (U1.F3)
CSI_D0_N: [17] - LVDS, CSI, LCD, TSC (R33.1), [07] - CPU - CSI, DISP (U1.E4)
CSI_D0_P: [17] - LVDS, CSI, LCD, TSC (R71.1), [07] - CPU - CSI, DISP (U1.E3)
CSI_D1_N: [17] - LVDS, CSI, LCD, TSC (R120.1), [07] - CPU - CSI, DISP (U1.D1)
CSI_D1_P: [17] - LVDS, CSI, LCD, TSC (R122.1), [07] - CPU - CSI, DISP (U1.D2)
CSI_GPIO0: [17] - LVDS, CSI, LCD, TSC (R129.1), [10] - CPU - GPIO, PWM, LEDS, BUTTONS (U1.A15)
CSI_GPIO1: [17] - LVDS, CSI, LCD, TSC (R136.1), [10] - CPU - GPIO, PWM, LEDS, BUTTONS (U1.B15)
CSPI1_CLK: [08] - CPU - SPI, UART (R43.2), [24] - HEADERS, UART (J2.23)
CSPI1_CS0: [08] - CPU - SPI, UART (U1.E22), [24] - HEADERS, UART (J2.24)
CSPI1_CS1: [08] - CPU - SPI, UART (U1.T22), [24] - HEADERS, UART (J2.26)
CSPI1_MISO: [08] - CPU - SPI, UART (U1.F21), [24] - HEADERS, UART (J2.21)
CSPI1_MOSI: [08] - CPU - SPI, UART (U1.D24), [24] - HEADERS, UART (J2.19)
CSPI2_CLK: [08] - CPU - SPI, UART (R130.2), [24] - HEADERS, UART (J2.38)
CSPI2_CS0: [08] - CPU - SPI, UART (U1.V25), [24] - HEADERS, UART (J2.35)
CSPI2_MISO: [08] - CPU - SPI, UART (U1.U24), [24] - HEADERS, UART (J2.40)
CSPI2_MOSI: [08] - CPU - SPI, UART (U1.T21), [24] - HEADERS, UART (J2.37)
CSPI3_CLK: [08] - CPU - SPI, UART (R131.2), [22] - SD CARD, SPI, FLASH, EEPROM, (R361.2 TP24.1 U15.6 U34.4)
CSPI3_CS0: [08] - CPU - SPI, UART (U1.P21), [22] - SD CARD, SPI, FLASH, EEPROM, (R364.2 TP25.1 U34.7)
CSPI3_CS2: [08] - CPU - SPI, UART (U1.R25), [22] - SD CARD, SPI, FLASH, EEPROM, (TP28.1 U15.1)
CSPI3_MCU_CLK: [14] - MCU (U6.19), [22] - SD CARD, SPI, FLASH, EEPROM, (R361.1 U34.13)
CSPI3_MCU_CS0: [14] - MCU (U6.8), [22] - SD CARD, SPI, FLASH, EEPROM, (R364.1 U34.10)
CSPI3_MCU_ENn: [08] - CPU - SPI, UART (R319.1 U1.M25), [22] - SD CARD, SPI, FLASH, EEPROM, (U34.14 U34.15)
CSPI3_MCU_MISO: [14] - MCU (U6.17), [22] - SD CARD, SPI, FLASH, EEPROM, (R363.1 U34.6)
CSPI3_MCU_MOSI: [14] - MCU (U6.18), [22] - SD CARD, SPI, FLASH, EEPROM, (R362.1 U34.12)
CSPI3_MISO: [08] - CPU - SPI, UART (U1.P23), [22] - SD CARD, SPI, FLASH, EEPROM, (R363.2 TP23.1 U15.2 U34.11)
CSPI3_MOSI: [08] - CPU - SPI, UART (U1.P22), [22] - SD CARD, SPI, FLASH, EEPROM, (R362.2 TP22.1 U15.5 U34.5)
ENET_LED_LINK: [15] - ETHERNET PHY (R81.2), [20] - ETHERNET, SATA (J6.13)
ENET_LED_RX: [15] - ETHERNET PHY (R82.2), [20] - ETHERNET, SATA (R287.2 R288.2)
ENET_REF_CLK: [06] - CPU - ETHERNET, SATA (U1.V22), [15] - ETHERNET PHY (R181.2)
FLEXCAN1_RX: [09] - CPU - SD, AUDIO, I2C, CAN (U1.D14), [23] - SENSORS, CAN, IR (R412.1 U20.4)
FLEXCAN1_STBY: [09] - CPU - SD, AUDIO, I2C, CAN (R280.1 U1.D15), [23] - SENSORS, CAN, IR (Q13.1 R413.1)
FLEXCAN1_TX: [09] - CPU - SD, AUDIO, I2C, CAN (U1.B13), [23] - SENSORS, CAN, IR (R411.1 U35.1 U35.2)
FLEXCAN2_RX: [09] - CPU - SD, AUDIO, I2C, CAN (U1.F14), [24] - HEADERS, UART (J2.16)
FLEXCAN2_TX: [09] - CPU - SD, AUDIO, I2C, CAN (U1.E14), [24] - HEADERS, UART (J2.15)
GPIO_OR_CLK: [10] - CPU - GPIO, PWM, LEDS, BUTTONS (U1.A17), [24] - HEADERS, UART (J2.7)
GPIO_OR_PWM_1: [10] - CPU - GPIO, PWM, LEDS, BUTTONS (U1.R22), [24] - HEADERS, UART (J2.29)
GPIO_OR_PWM_2: [10] - CPU - GPIO, PWM, LEDS, BUTTONS (U1.T25), [24] - HEADERS, UART (R368.1 R369.1)
GPIO_OR_PWM_3: [10] - CPU - GPIO, PWM, LEDS, BUTTONS (U1.B19), [24] - HEADERS, UART (J2.32)
GPIO_OR_PWM_4: [10] - CPU - GPIO, PWM, LEDS, BUTTONS (U1.F17), [24] - HEADERS, UART (J2.33)
GYRO_INT: [10] - CPU - GPIO, PWM, LEDS, BUTTONS (R410.1 U1.N24), [23] - SENSORS, CAN, IR (R313.2 R314.2)
HDMI_CEC_IN: [05] - CPU - HDMI, LVDS (R24.2 R25.2 R118.1), [16] - HDMI (U12.16)
HDMI_CLK_N: [05] - CPU - HDMI, LVDS (U1.J5), [16] - HDMI (J5.12 U12.15 U12.24)
HDMI_CLK_P: [05] - CPU - HDMI, LVDS (U1.J6), [16] - HDMI (J5.10 U12.13 U12.26)
HDMI_D0_N: [05] - CPU - HDMI, LVDS (U1.K5), [16] - HDMI (J5.9 U12.12 U12.27)
HDMI_D0_P: [05] - CPU - HDMI, LVDS (U1.K6), [16] - HDMI (J5.7 U12.10 U12.29)
HDMI_D1_N: [05] - CPU - HDMI, LVDS (U1.J3), [16] - HDMI (J5.6 U12.9 U12.30)
HDMI_D1_P: [05] - CPU - HDMI, LVDS (U1.J4), [16] - HDMI (J5.4 U12.7 U12.32)
HDMI_D2_N: [05] - CPU - HDMI, LVDS (U1.K3), [16] - HDMI (J5.3 U12.6 U12.33)
HDMI_D2_P: [05] - CPU - HDMI, LVDS (U1.K4), [16] - HDMI (J5.1 U12.4 U12.35)
HDMI_HPD: [05] - CPU - HDMI, LVDS (R23.2), [16] - HDMI (R357.2 U33.4)
I2C1_SCL: [09] - CPU - SD, AUDIO, I2C, CAN (R132.1 U1.H20), [26] - PWR PMIC (R238.1), [22] - SD CARD, SPI, FLASH, EEPROM, (U18.6), [23] - SENSORS, CAN, IR (U22.4 U28.11), [24] - HEADERS, UART (R278.1)
I2C1_SCL_MCU: [14] - MCU (R291.1 U6.10), [24] - HEADERS, UART (R279.1)
I2C1_SDA: [09] - CPU - SD, AUDIO, I2C, CAN (R28.1 U1.G23), [26] - PWR PMIC (R247.1), [22] - SD CARD, SPI, FLASH, EEPROM, (U18.5), [23] - SENSORS, CAN, IR (U22.6 U28.12), [24] - HEADERS, UART (R276.1)
I2C1_SDA_MCU: [14] - MCU (R290.1 U6.11), [24] - HEADERS, UART (R277.1)
I2C2_SCL: [17] - LVDS, CSI, LCD, TSC (R154.1), [09] - CPU - SD, AUDIO, I2C, CAN (R134.1 U1.U5), [18] - PCIE MINI (J15.30), [23] - SENSORS, CAN, IR (U24.1 U26.6), [16] - HDMI (U12.17), [21] - AUDIO (U14.29), [24] - HEADERS, UART (J2.28)
I2C2_SDA: [17] - LVDS, CSI, LCD, TSC (R156.1), [09] - CPU - SD, AUDIO, I2C, CAN (R133.1 U1.T7), [18] - PCIE MINI (J15.32), [23] - SENSORS, CAN, IR (U24.6 U26.1), [16] - HDMI (U12.18), [21] - AUDIO (U14.27), [24] - HEADERS, UART (J2.27)
I2C3_SCL: [17] - LVDS, CSI, LCD, TSC (R196.2), [09] - CPU - SD, AUDIO, I2C, CAN (R142.1 U1.R4), [24] - HEADERS, UART (J2.5)
I2C3_SDA: [17] - LVDS, CSI, LCD, TSC (R195.2), [09] - CPU - SD, AUDIO, I2C, CAN (R137.1 U1.R2), [24] - HEADERS, UART (J2.3)
IR_RCV: [10] - CPU - GPIO, PWM, LEDS, BUTTONS (U1.A20), [23] - SENSORS, CAN, IR (U23.1)
LVDS0_CLK_N: [17] - LVDS, CSI, LCD, TSC (R135.1), [05] - CPU - HDMI, LVDS (U1.V4)
LVDS0_CLK_P: [17] - LVDS, CSI, LCD, TSC (R138.1), [05] - CPU - HDMI, LVDS (U1.V3)
LVDS0_TX0_N: [17] - LVDS, CSI, LCD, TSC (R65.1), [05] - CPU - HDMI, LVDS (U1.U2)
LVDS0_TX0_P: [17] - LVDS, CSI, LCD, TSC (R119.1), [05] - CPU - HDMI, LVDS (U1.U1)
LVDS0_TX1_N: [17] - LVDS, CSI, LCD, TSC (R121.1), [05] - CPU - HDMI, LVDS (U1.U4)
LVDS0_TX1_P: [17] - LVDS, CSI, LCD, TSC (R123.1), [05] - CPU - HDMI, LVDS (U1.U3)
LVDS0_TX2_N: [17] - LVDS, CSI, LCD, TSC (R126.1), [05] - CPU - HDMI, LVDS (U1.V2)
LVDS0_TX2_P: [17] - LVDS, CSI, LCD, TSC (R128.1), [05] - CPU - HDMI, LVDS (U1.V1)
LVDS0_TX3_N: [17] - LVDS, CSI, LCD, TSC (TP19.1), [05] - CPU - HDMI, LVDS (U1.W2)
LVDS0_TX3_P: [17] - LVDS, CSI, LCD, TSC (TP20.1), [05] - CPU - HDMI, LVDS (U1.W1)
MCU_BTN: [14] - MCU (R390.2), [25] - LEDS, BUTTONS (C314.1 D35.1 R149.1)
MCU_ISPn: [10] - CPU - GPIO, PWM, LEDS, BUTTONS (R213.1 U1.B21), [14] - MCU (R204.2)
MCU_RSTINn: [10] - CPU - GPIO, PWM, LEDS, BUTTONS (R212.1 U1.A21), [14] - MCU (U21.1 U21.2)
MCU_RSTOUTn: [11] - CPU - JTAG, CONTROL (R93.1), [14] - MCU (U6.16)
MCU_SWDIO: [10] - CPU - GPIO, PWM, LEDS, BUTTONS (TP31.1 U1.P1), [14] - MCU (U25.3)
MCU_SWDIO_SEL: [10] - CPU - GPIO, PWM, LEDS, BUTTONS (R289.1 U1.N2), [14] - MCU (U25.6)
PCIE_CLK_N: [04] - CPU - PCIE, USB (C66.2 R17.2), [18] - PCIE MINI (J15.11)
PCIE_CLK_P: [04] - CPU - PCIE, USB (C67.2 R16.2), [18] - PCIE MINI (J15.13)
PCIE_RSTn: [11] - CPU - JTAG, CONTROL (R158.2 R170.1), [18] - PCIE MINI (J15.22)
PCIE_RSTn_R: [04] - CPU - PCIE, USB (U1.V5), [11] - CPU - JTAG, CONTROL (R170.2)
PCIE_RX_N: [04] - CPU - PCIE, USB (U1.B1), [18] - PCIE MINI (J15.23)
PCIE_RX_P: [04] - CPU - PCIE, USB (U1.B2), [18] - PCIE MINI (J15.25)
PCIE_TX_N: [04] - CPU - PCIE, USB (C63.2), [18] - PCIE MINI (J15.31)
PCIE_TX_P: [04] - CPU - PCIE, USB (C65.2), [18] - PCIE MINI (J15.33)
PCIE_WAKE: [04] - CPU - PCIE, USB (U1.P3), [18] - PCIE MINI (J15.1 R197.1)
PCIE_WDISn: [04] - CPU - PCIE, USB (R116.1 U1.R1), [18] - PCIE MINI (J15.20)
PMIC_INT: [11] - CPU - JTAG, CONTROL (U1.T24), [26] - PWR PMIC (R236.2 R263.1 U9.1)
PMIC_STBY_REQ: [11] - CPU - JTAG, CONTROL (D28.2), [14] - MCU (D36.2), [26] - PWR PMIC (R237.2 R385.1 U9.4)
POK_1V375_OPT: [11] - CPU - JTAG, CONTROL (R351.1), [27] - PWR 1V375 OPT, 3V3 OPT (U30.3)
POK_3V3_OPT: [11] - CPU - JTAG, CONTROL (R333.1), [27] - PWR 1V375 OPT, 3V3 OPT (R405.1 U36.3)
POK_PMIC: [11] - CPU - JTAG, CONTROL (R177.1), [26] - PWR PMIC (R229.1 U9.3), [27] - PWR 1V375 OPT, 3V3 OPT (R404.2)
POK_SYS: [11] - CPU - JTAG, CONTROL (5 pins), [15] - ETHERNET PHY (U32.9), [25] - LEDS, BUTTONS (Q4.1)
PWRON: [11] - CPU - JTAG, CONTROL (D29.2), [25] - LEDS, BUTTONS (D39.2), [26] - PWR PMIC (R262.1 TP6.1 U9.56)
RGMII_INT: [06] - CPU - ETHERNET, SATA (R88.2 U1.W22), [15] - ETHERNET PHY (R89.1 TP27.1 U7.38)
RGMII_MDC: [06] - CPU - ETHERNET, SATA (U1.V20), [15] - ETHERNET PHY (R85.1 R87.1)
RGMII_MDIO: [06] - CPU - ETHERNET, SATA (U1.V23), [15] - ETHERNET PHY (R86.1 R162.1)
RGMII_RSTn: [11] - CPU - JTAG, CONTROL (D10.2 R180.1), [15] - ETHERNET PHY (R75.1 U7.42)
RGMII_RXCLK: [06] - CPU - ETHERNET, SATA (U1.B25), [15] - ETHERNET PHY (R83.1)
RGMII_RXD0: [06] - CPU - ETHERNET, SATA (U1.C24), [15] - ETHERNET PHY (R98.1 U7.32)
RGMII_RXD1: [06] - CPU - ETHERNET, SATA (U1.B23), [15] - ETHERNET PHY (R97.1 U7.31)
RGMII_RXD2: [06] - CPU - ETHERNET, SATA (U1.B24), [15] - ETHERNET PHY (R96.1 U7.28)
RGMII_RXD3: [06] - CPU - ETHERNET, SATA (U1.D23), [15] - ETHERNET PHY (R95.1 U7.27)
RGMII_RXDV: [06] - CPU - ETHERNET, SATA (U1.D22), [15] - ETHERNET PHY (R91.1 U7.33)
RGMII_TXCLK: [06] - CPU - ETHERNET, SATA (R35.2), [15] - ETHERNET PHY (U7.24)
RGMII_TXD0: [06] - CPU - ETHERNET, SATA (U1.C22), [15] - ETHERNET PHY (U7.19)
RGMII_TXD1: [06] - CPU - ETHERNET, SATA (U1.F20), [15] - ETHERNET PHY (U7.20)
RGMII_TXD2: [06] - CPU - ETHERNET, SATA (U1.E21), [15] - ETHERNET PHY (U7.21)
RGMII_TXD3: [06] - CPU - ETHERNET, SATA (U1.A24), [15] - ETHERNET PHY (U7.22)
RGMII_TXEN: [06] - CPU - ETHERNET, SATA (U1.C23), [15] - ETHERNET PHY (U7.25)
RST_BTN_HDR: [25] - LEDS, BUTTONS (5 pins), [24] - HEADERS, UART (J1.15)
RSTINn: [11] - CPU - JTAG, CONTROL (R68.1 U8.1), [25] - LEDS, BUTTONS (R348.2)
RSTOUTn: [11] - CPU - JTAG, CONTROL (R144.2 U11.4), [19] - USB (R218.2), [14] - MCU (R281.2), [28] - PWR IN, MECH, DOC (R155.2), [23] - SENSORS, CAN, IR (R318.1 U29.2), [24] - HEADERS, UART (J1.14)
SATA_RX_N: [06] - CPU - ETHERNET, SATA (C69.2), [20] - ETHERNET, SATA (J8.5)
SATA_RX_P: [06] - CPU - ETHERNET, SATA (C70.2), [20] - ETHERNET, SATA (J8.6)
SATA_TX_N: [06] - CPU - ETHERNET, SATA (C71.2), [20] - ETHERNET, SATA (J8.3)
SATA_TX_P: [06] - CPU - ETHERNET, SATA (C72.2), [20] - ETHERNET, SATA (J8.2)
SD2_ACT: [09] - CPU - SD, AUDIO, I2C, CAN (U1.T3), [22] - SD CARD, SPI, FLASH, EEPROM, (Q6.1)
SD2_CD: [09] - CPU - SD, AUDIO, I2C, CAN (R150.1 U1.R6), [22] - SD CARD, SPI, FLASH, EEPROM, (Q3.3)
SD2_CLK: [09] - CPU - SD, AUDIO, I2C, CAN (R153.2), [22] - SD CARD, SPI, FLASH, EEPROM, (J13.5)
SD2_CMD: [09] - CPU - SD, AUDIO, I2C, CAN (R143.1 R152.2), [22] - SD CARD, SPI, FLASH, EEPROM, (J13.3)
SD2_DATA0: [09] - CPU - SD, AUDIO, I2C, CAN (U1.A22), [22] - SD CARD, SPI, FLASH, EEPROM, (J13.7)
SD2_DATA1: [09] - CPU - SD, AUDIO, I2C, CAN (U1.E20), [22] - SD CARD, SPI, FLASH, EEPROM, (J13.8)
SD2_DATA2: [09] - CPU - SD, AUDIO, I2C, CAN (U1.A23), [22] - SD CARD, SPI, FLASH, EEPROM, (J13.1)
SD2_DATA3: [09] - CPU - SD, AUDIO, I2C, CAN (U1.B22), [22] - SD CARD, SPI, FLASH, EEPROM, (J13.2)
SD2_WP: [09] - CPU - SD, AUDIO, I2C, CAN (R151.1 U1.T1), [22] - SD CARD, SPI, FLASH, EEPROM, (R139.2)
TEMP_ALERT: [10] - CPU - GPIO, PWM, LEDS, BUTTONS (R257.1 U1.E24), [23] - SENSORS, CAN, IR (U24.3)
TRD0_N: [15] - ETHERNET PHY (U7.3), [20] - ETHERNET, SATA (J6.10)
TRD0_P: [15] - ETHERNET PHY (U7.2), [20] - ETHERNET, SATA (J6.11)
TRD1_N: [15] - ETHERNET PHY (U7.6), [20] - ETHERNET, SATA (J6.5)
TRD1_P: [15] - ETHERNET PHY (U7.5), [20] - ETHERNET, SATA (J6.4)
TRD2_N: [15] - ETHERNET PHY (U7.8), [20] - ETHERNET, SATA (J6.2)
TRD2_P: [15] - ETHERNET PHY (U7.7), [20] - ETHERNET, SATA (J6.3)
TRD3_N: [15] - ETHERNET PHY (U7.11), [20] - ETHERNET, SATA (J6.9)
TRD3_P: [15] - ETHERNET PHY (U7.10), [20] - ETHERNET, SATA (J6.8)
TS_X+: [17] - LVDS, CSI, LCD, TSC (D37.5 J10.1), [14] - MCU (C177.1 FB15.2)
TS_X-: [17] - LVDS, CSI, LCD, TSC (D37.1 J10.2), [14] - MCU (C178.1 FB25.2)
TS_Y+: [17] - LVDS, CSI, LCD, TSC (D37.4 J10.4), [14] - MCU (C210.1 FB28.2)
TS_Y-: [17] - LVDS, CSI, LCD, TSC (D37.3 J10.3), [14] - MCU (C179.1 FB27.2)
UART1_CTS: [08] - CPU - SPI, UART (U1.G21), [24] - HEADERS, UART (Q8.4 R60.1 R375.1)
UART1_RTS: [08] - CPU - SPI, UART (U1.G20), [24] - HEADERS, UART (Q11.1 R376.1 R378.1)
UART1_RXD: [08] - CPU - SPI, UART (U1.M3), [24] - HEADERS, UART (Q8.1 R370.1 R373.1)
UART1_TXD: [08] - CPU - SPI, UART (U1.M1), [24] - HEADERS, UART (Q11.4 R371.1 R374.1)
UART2_RXD: [08] - CPU - SPI, UART (U1.D13), [14] - MCU (TP30.1 U6.32)
UART2_TXD: [08] - CPU - SPI, UART (U1.C13), [14] - MCU (TP29.1 U6.31)
UART3_CTS: [08] - CPU - SPI, UART (U1.D25), [24] - HEADERS, UART (J2.36)
UART3_RTS: [08] - CPU - SPI, UART (U1.F23), [24] - HEADERS, UART (J2.11)
UART3_RXD: [08] - CPU - SPI, UART (U1.G22), [24] - HEADERS, UART (J2.10)
UART3_TXD: [08] - CPU - SPI, UART (U1.F22), [24] - HEADERS, UART (J2.8)
UART4_RXD: [08] - CPU - SPI, UART (U1.V6), [24] - HEADERS, UART (J2.13)
UART4_TXD: [08] - CPU - SPI, UART (U1.W5), [24] - HEADERS, UART (R366.1 R367.1)
UART5_RXD: [08] - CPU - SPI, UART (U1.U6), [24] - HEADERS, UART (J2.18)
UART5_TXD: [08] - CPU - SPI, UART (U1.U7), [24] - HEADERS, UART (J2.22)
USB0_ID: [04] - CPU - PCIE, USB (U1.T4), [19] - USB (D19.1 J11.4 R198.1 R199.2), [28] - PWR IN, MECH, DOC (U16.2)
USB0_ID_BUFF_EN: [04] - CPU - PCIE, USB (R305.2 U1.H21), [28] - PWR IN, MECH, DOC (R304.2)
USB0_N: [04] - CPU - PCIE, USB (U1.B6), [19] - USB (R322.2 R323.2)
USB0_P: [04] - CPU - PCIE, USB (U1.A6), [19] - USB (R325.2 R326.2)
USB1_N: [04] - CPU - PCIE, USB (U1.F10), [19] - USB (R328.2 R329.2)
USB1_P: [04] - CPU - PCIE, USB (U1.E10), [19] - USB (R331.2 R332.2)
USB_HDR_N: [19] - USB (R194.2 R207.1), [24] - HEADERS, UART (L7.3)
USB_HDR_P: [19] - USB (R297.2 R298.1), [24] - HEADERS, UART (L7.4)
USB_MCU_N: [19] - USB (R207.2 R294.2), [14] - MCU (R299.2)
USB_MCU_P: [19] - USB (R295.1 R298.2), [14] - MCU (R300.2 R387.2)
USB_MPCIE_N: [18] - PCIE MINI (L6.4), [19] - USB (U13.8)
USB_MPCIE_P: [18] - PCIE MINI (L6.3), [19] - USB (U13.9)
USER_BTN_1: [10] - CPU - GPIO, PWM, LEDS, BUTTONS (U1.C15), [25] - LEDS, BUTTONS (D35.2 R381.1)
USER_BTN_2: [10] - CPU - GPIO, PWM, LEDS, BUTTONS (U1.A16), [25] - LEDS, BUTTONS (C315.1 R254.1)
USER_BTN_3: [10] - CPU - GPIO, PWM, LEDS, BUTTONS (U1.E15), [25] - LEDS, BUTTONS (C316.1 R255.1)
USER_LED: [11] - CPU - JTAG, CONTROL (U1.E19), [25] - LEDS, BUTTONS (Q12.1)
USER_LED_1: [10] - CPU - GPIO, PWM, LEDS, BUTTONS (U1.A18), [14] - MCU (U6.30), [25] - LEDS, BUTTONS (R145.2)
USER_LED_2: [10] - CPU - GPIO, PWM, LEDS, BUTTONS (U1.C17), [14] - MCU (R389.2), [25] - LEDS, BUTTONS (R165.2)
USER_LED_3: [10] - CPU - GPIO, PWM, LEDS, BUTTONS (U1.F16), [14] - MCU (R391.2), [25] - LEDS, BUTTONS (R176.2)
USER_LED_4: [10] - CPU - GPIO, PWM, LEDS, BUTTONS (U1.D17), [14] - MCU (R392.2), [25] - LEDS, BUTTONS (R189.2)
USER_LED_5: [10] - CPU - GPIO, PWM, LEDS, BUTTONS (U1.A19), [25] - LEDS, BUTTONS (R192.2)
USER_LED_6: [10] - CPU - GPIO, PWM, LEDS, BUTTONS (U1.B18), [25] - LEDS, BUTTONS (R193.2)
USER_LED_7: [10] - CPU - GPIO, PWM, LEDS, BUTTONS (U1.E17), [25] - LEDS, BUTTONS (R200.2)
USER_LED_8: [10] - CPU - GPIO, PWM, LEDS, BUTTONS (U1.C18), [25] - LEDS, BUTTONS (R202.2)
VID_IN_CSI1_D0: [17] - LVDS, CSI, LCD, TSC (J7.9), [07] - CPU - CSI, DISP (U1.M21)
VID_IN_CSI1_D1: [17] - LVDS, CSI, LCD, TSC (J7.10), [07] - CPU - CSI, DISP (U1.L24)
VID_IN_CSI1_D2: [17] - LVDS, CSI, LCD, TSC (J7.11), [07] - CPU - CSI, DISP (U1.L25)
VID_IN_CSI1_D3: [17] - LVDS, CSI, LCD, TSC (J7.12), [07] - CPU - CSI, DISP (U1.K25)
VID_IN_CSI1_D4: [17] - LVDS, CSI, LCD, TSC (J7.14), [07] - CPU - CSI, DISP (U1.L23)
VID_IN_CSI1_D5: [17] - LVDS, CSI, LCD, TSC (J7.15), [07] - CPU - CSI, DISP (U1.L22)
VID_IN_CSI1_D6: [17] - LVDS, CSI, LCD, TSC (J7.16), [07] - CPU - CSI, DISP (U1.K24)
VID_IN_CSI1_D7: [17] - LVDS, CSI, LCD, TSC (J7.17), [07] - CPU - CSI, DISP (U1.L21)
VID_IN_CSI1_D8: [17] - LVDS, CSI, LCD, TSC (J7.19), [07] - CPU - CSI, DISP (U1.J25)
VID_IN_CSI1_D9: [17] - LVDS, CSI, LCD, TSC (J7.20), [07] - CPU - CSI, DISP (U1.L20)
VID_IN_CSI1_D10: [17] - LVDS, CSI, LCD, TSC (J7.21), [07] - CPU - CSI, DISP (U1.K23)
VID_IN_CSI1_D11: [17] - LVDS, CSI, LCD, TSC (J7.22), [07] - CPU - CSI, DISP (U1.K21)
VID_IN_CSI1_D12: [17] - LVDS, CSI, LCD, TSC (J7.24), [07] - CPU - CSI, DISP (U1.G24)
VID_IN_CSI1_D13: [17] - LVDS, CSI, LCD, TSC (J7.25), [07] - CPU - CSI, DISP (U1.J22)
VID_IN_CSI1_D14: [17] - LVDS, CSI, LCD, TSC (J7.26), [07] - CPU - CSI, DISP (U1.G25)
VID_IN_CSI1_D15: [17] - LVDS, CSI, LCD, TSC (J7.27), [07] - CPU - CSI, DISP (U1.H22)
VID_IN_CSI1_D16: [17] - LVDS, CSI, LCD, TSC (J7.29), [07] - CPU - CSI, DISP (U1.H23)
VID_IN_CSI1_D17: [17] - LVDS, CSI, LCD, TSC (J7.30), [07] - CPU - CSI, DISP (U1.F24)
VID_IN_CSI1_D18: [17] - LVDS, CSI, LCD, TSC (J7.31), [07] - CPU - CSI, DISP (U1.J21)
VID_IN_CSI1_D19: [17] - LVDS, CSI, LCD, TSC (J7.32), [07] - CPU - CSI, DISP (U1.F25)
VID_IN_CSI1_DE: [17] - LVDS, CSI, LCD, TSC (J7.34), [07] - CPU - CSI, DISP (U1.M22)
VID_IN_CSI1_HSYNC: [17] - LVDS, CSI, LCD, TSC (J7.6), [07] - CPU - CSI, DISP (U1.M20)
VID_IN_CSI1_INT: [17] - LVDS, CSI, LCD, TSC (J7.35), [07] - CPU - CSI, DISP (U1.K22)
VID_IN_CSI1_INT2: [17] - LVDS, CSI, LCD, TSC (J7.36), [07] - CPU - CSI, DISP (U1.M23)
VID_IN_CSI1_PIXCLK: [17] - LVDS, CSI, LCD, TSC (R275.1), [07] - CPU - CSI, DISP (U1.H25)
VID_IN_CSI1_RSTn: [17] - LVDS, CSI, LCD, TSC (J7.37), [11] - CPU - JTAG, CONTROL (R178.1 R179.1)
VID_IN_CSI1_RSTn_R: [11] - CPU - JTAG, CONTROL (R179.2), [07] - CPU - CSI, DISP (U1.N22)
VID_IN_CSI1_VSYNC: [17] - LVDS, CSI, LCD, TSC (J7.7), [07] - CPU - CSI, DISP (U1.M24)

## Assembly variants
Production: not fitted C177 C178 C179 C210 C237 C252 C263 C264 C327 C328 C390 C391 C392 C393 C406 C407 C408 C409 C410 C411 C416 C417 C418 C432 C433 D4 D8 D28 D29 D30 D31 D32 D36 D38 D39 FB2 FB8 FB17 FB20 FB26 FB29 FB32 FB35 FB38 FB41 FB42 FB43 L12 LINK1 LINK2 Q14 R15 R21 R24 R41 R52 R53 R54 R57 R58 R60 R65 R67 R68 R70 R87 R93 R104 R110 R114 R117 R119 R121 R123 R126 R128 R135 R138 R147 R148 R158 R159 R167 R168 R171 R174 R177 R178 R182 R191 R197 R199 R203 R207 R208 R209 R210 R211 R215 R216 R217 R234 R236 R239 R245 R250 R258 R261 R266 R271 R272 R274 R281 R282 R287 R290 R291 R294 R295 R298 R304 R310 R313 R316 R322 R325 R328 R331 R334 R335 R336 R337 R338 R339 R340 R341 R342 R343 R344 R347 R350 R352 R355 R357 R359 R360 R365 R367 R368 R371 R373 R374 R376 R378 R383 R385 R386 R387 R388 R392 R393 R394 R395 R396 R400 R401 R403 R408 R411 R412 R413 U17 U30 U34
